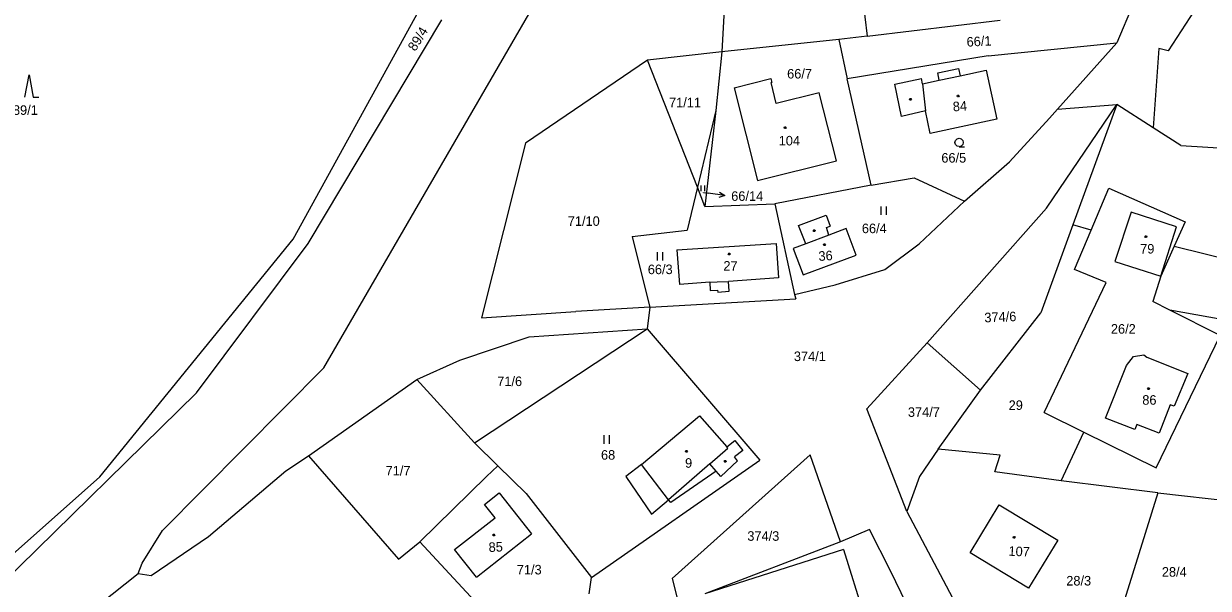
# Model space of a CAD drawing. Extents: x -811039 to -805820, y -1161436 to -1155864.
# Drawn here: x -806771.7 to -806560.9, y -1158236.2 to -1158135.7 of the extents above; entities that cross this region are included whole.
import ezdxf

# ---------------------------------------------------------------- set-up
doc = ezdxf.new("R2010")
doc.units = 0
for name, color, linetype in [('Default', 7, 'Continuous'), ('KN_HRANICE', 7, 'Continuous'), ('KN_KULTURY', 7, 'Continuous'), ('KN_PARCELY', 7, 'Continuous'), ('KN_SLUCKY', 7, 'Continuous')]:
    doc.layers.add(name, color=color, linetype=linetype)

# ---------------------------------------------------------------- blocks, each defined once
blk = doc.blocks.new('304')
at = {"layer": 'Default'}
blk.add_lwpolyline([(0, 0), (-0.38, 0.1), (-0.65, 0.37), (-0.75, 0.74), (-0.65, 1.11), (-0.38, 1.38), (-0.01, 1.48), (0.36, 1.38), (0.63, 1.11), (0.73, 0.73), (0.63, 0.35), (0.36, 0.08), (-0.02, -0.02), (0.98, -0.02)], dxfattribs=at)
blk = doc.blocks.new('306')
at = {"layer": 'Default'}
for p, q in [((-0.5, 1.5), (-0.5, 0)), ((0.5, 0), (0.5, 1.5))]:
    blk.add_line(p, q, dxfattribs=at)
blk = doc.blocks.new('308')
at = {"layer": 'Default'}
blk.add_lwpolyline([(-0.75, 0), (0, 4), (0.75, 0), (1.75, 0)], dxfattribs=at)
blk = doc.blocks.new('10292')
at = {"layer": 'Default'}
blk.add_line((0, 3), (0, 0), dxfattribs=at)
blk.add_lwpolyline([(-0.5, 2), (0, 3), (0.5, 2)], dxfattribs=at)
blk = doc.blocks.new('402')
at = {"layer": 'Default'}
blk.add_lwpolyline([(0.09, 0.15), (0.18, 0), (0.09, -0.15), (-0.09, -0.15), (-0.18, 0), (-0.09, 0.15), (0.09, 0.15)], dxfattribs=at)

msp = doc.modelspace()

# ---------------------------------------------------------------- linework, layer by layer
at = {"layer": 'KN_HRANICE'}
for p, q in [((-806625.5, -1158104.42), (-806621.6, -1158137.92)), ((-806723.74, -1158174.06), (-806693.13, -1158118.44)), ((-806646.33, -1158121.28), (-806647.48, -1158140.75)), ((-806558.78, -1158126.18), (-806568.02, -1158140.53)), ((-806718.26, -1158196.99), (-806677.82, -1158127.15)), ((-806574.25, -1158132.24), (-806577.2, -1158139.11)), ((-806721.04, -1158174.85), (-806697.27, -1158135.03)), ((-806621.6, -1158137.92), (-806597.92, -1158135.1)), ((-806626.66, -1158138.55), (-806647.48, -1158140.75)), ((-806621.6, -1158137.92), (-806626.66, -1158138.55)), ((-806626.66, -1158138.55), (-806625.14, -1158145.51)), ((-806600.08, -1158141.46), (-806577.2, -1158139.11)), ((-806587.74, -1158150.92), (-806577.2, -1158139.11)), ((-806647.48, -1158140.75), (-806660.66, -1158142.19)), ((-806647.48, -1158140.75), (-806648.51, -1158151.16)), ((-806569.67, -1158140.13), (-806570.68, -1158154.28)), ((-806568.02, -1158140.53), (-806569.67, -1158140.13)), ((-806660.66, -1158142.19), (-806682.39, -1158156.98)), ((-806651.8, -1158164.84), (-806660.66, -1158142.19)), ((-806600.08, -1158141.46), (-806625.14, -1158145.51)), ((-806645.27, -1158147.12), (-806638.76, -1158145.49)), ((-806638.76, -1158145.49), (-806638.59, -1158146.19)), ((-806620.86, -1158164.46), (-806625.14, -1158145.51)), ((-806616.67, -1158146.5), (-806611.94, -1158145.48)), ((-806611.75, -1158146.41), (-806611.94, -1158145.48)), ((-806609.04, -1158144.44), (-806605.35, -1158143.69)), ((-806608.8, -1158145.74), (-806609.04, -1158144.44)), ((-806605.35, -1158143.69), (-806605.07, -1158144.98)), ((-806605.07, -1158144.98), (-806600.43, -1158143.97)), ((-806600.43, -1158143.97), (-806598.53, -1158152.7)), ((-806645.27, -1158147.12), (-806641.11, -1158163.62)), ((-806638.59, -1158146.19), (-806638.69, -1158146.21)), ((-806637.77, -1158149.94), (-806638.69, -1158146.21)), ((-806615.49, -1158152.21), (-806616.67, -1158146.5)), ((-806611.75, -1158146.41), (-806608.8, -1158145.74)), ((-806630.11, -1158148.03), (-806637.77, -1158149.94)), ((-806627.08, -1158160.11), (-806630.11, -1158148.03)), ((-806648.51, -1158151.16), (-806651.8, -1158164.84)), ((-806648.51, -1158151.16), (-806650.46, -1158168.28)), ((-806611.24, -1158151.25), (-806615.49, -1158152.21)), ((-806610.39, -1158155.24), (-806611.24, -1158151.25)), ((-806589.71, -1158168.58), (-806577.19, -1158150.1)), ((-806589.16, -1158152.51), (-806587.74, -1158150.92)), ((-806587.74, -1158150.92), (-806577.19, -1158150.1)), ((-806577.19, -1158150.1), (-806584.99, -1158171.53)), ((-806570.68, -1158154.28), (-806577.19, -1158150.1)), ((-806598.53, -1158152.7), (-806610.39, -1158155.24)), ((-806596.26, -1158160.32), (-806589.16, -1158152.51)), ((-806565.79, -1158157.41), (-806570.68, -1158154.28)), ((-806682.39, -1158156.98), (-806690.22, -1158188.05)), ((-806565.79, -1158157.41), (-806554.8, -1158158.09)), ((-806641.11, -1158163.62), (-806627.08, -1158160.11)), ((-806604.3, -1158167.3), (-806596.26, -1158160.32)), ((-806620.86, -1158164.46), (-806638, -1158167.77)), ((-806620.86, -1158164.46), (-806613.26, -1158163.16)), ((-806613.26, -1158163.16), (-806604.3, -1158167.3)), ((-806651.8, -1158164.84), (-806653.63, -1158172.45)), ((-806650.46, -1158168.28), (-806651.8, -1158164.84)), ((-806581.74, -1158172.46), (-806578.57, -1158164.97)), ((-806578.57, -1158164.97), (-806565.02, -1158170.97)), ((-806650.46, -1158168.28), (-806638, -1158167.77)), ((-806638, -1158167.77), (-806634.51, -1158183.94)), ((-806604.3, -1158167.3), (-806612.34, -1158174.92)), ((-806610.94, -1158192.5), (-806589.71, -1158168.58)), ((-806633.81, -1158171.63), (-806628.89, -1158169.81)), ((-806628.89, -1158169.81), (-806628.2, -1158171.77)), ((-806574.65, -1158169.26), (-806577.5, -1158178.04)), ((-806566.53, -1158171.88), (-806574.65, -1158169.26)), ((-806663.42, -1158173.62), (-806653.63, -1158172.45)), ((-806632.51, -1158174.87), (-806633.81, -1158171.63)), ((-806628.81, -1158171.99), (-806628.2, -1158171.77)), ((-806628.42, -1158173.33), (-806628.81, -1158171.99)), ((-806625.31, -1158172.15), (-806628.42, -1158173.33)), ((-806623.58, -1158176.91), (-806625.31, -1158172.15)), ((-806584.99, -1158171.53), (-806590.67, -1158187.16)), ((-806581.74, -1158172.46), (-806584.99, -1158171.53)), ((-806584.71, -1158179.46), (-806581.74, -1158172.46)), ((-806569.37, -1158180.66), (-806566.53, -1158171.88)), ((-806565.02, -1158170.97), (-806566.96, -1158175.3)), ((-806758.12, -1158216.37), (-806723.74, -1158174.06)), ((-806740.96, -1158201.43), (-806721.04, -1158174.85)), ((-806663.42, -1158173.62), (-806661.2, -1158182.44)), ((-806655.48, -1158175.94), (-806637.79, -1158174.85)), ((-806637.79, -1158174.85), (-806637.37, -1158180.94)), ((-806632.51, -1158174.87), (-806634.77, -1158175.72)), ((-806618.45, -1158179.46), (-806612.34, -1158174.92)), ((-806655.48, -1158175.94), (-806654.99, -1158182.11)), ((-806634.77, -1158175.72), (-806633.01, -1158180.44)), ((-806633.01, -1158180.44), (-806623.58, -1158176.91)), ((-806566.96, -1158175.3), (-806569.37, -1158180.66)), ((-806566.96, -1158175.3), (-806533.49, -1158183.62)), ((-806577.5, -1158178.04), (-806569.37, -1158180.66)), ((-806637.37, -1158180.94), (-806646.27, -1158181.59)), ((-806627.29, -1158182.21), (-806618.45, -1158179.46)), ((-806579.07, -1158181.81), (-806584.71, -1158179.46)), ((-806569.37, -1158180.66), (-806570.79, -1158185.17)), ((-806661.2, -1158182.44), (-806660.25, -1158186.2)), ((-806649.57, -1158181.75), (-806654.99, -1158182.11)), ((-806649.57, -1158181.75), (-806649.53, -1158183.19)), ((-806649.53, -1158183.19), (-806648.24, -1158183.14)), ((-806648.24, -1158183.14), (-806648.19, -1158183.48)), ((-806648.19, -1158183.48), (-806646.13, -1158183.34)), ((-806646.13, -1158183.34), (-806646.27, -1158181.59)), ((-806634.51, -1158183.94), (-806627.29, -1158182.21)), ((-806590.13, -1158204.94), (-806579.07, -1158181.81)), ((-806660.25, -1158186.2), (-806634.28, -1158184.71)), ((-806634.51, -1158183.94), (-806634.28, -1158184.71)), ((-806567.76, -1158186.7), (-806570.79, -1158185.17)), ((-806690.22, -1158188.05), (-806673.44, -1158186.95)), ((-806660.25, -1158186.2), (-806673.44, -1158186.95)), ((-806660.25, -1158186.2), (-806660.73, -1158190.04)), ((-806601.46, -1158200.93), (-806590.67, -1158187.16)), ((-806535.97, -1158192.47), (-806567.76, -1158186.7)), ((-806558.81, -1158191.24), (-806567.76, -1158186.7)), ((-806694.06, -1158195.61), (-806681.77, -1158191.44)), ((-806691.48, -1158210.33), (-806660.73, -1158190.04)), ((-806681.77, -1158191.44), (-806660.73, -1158190.04)), ((-806660.73, -1158190.04), (-806640.69, -1158213.39)), ((-806570.15, -1158214.79), (-806558.81, -1158191.24)), ((-806621.66, -1158204.29), (-806610.94, -1158192.5)), ((-806610.94, -1158192.5), (-806601.46, -1158200.93)), ((-806701.73, -1158199.05), (-806694.06, -1158195.61)), ((-806575.43, -1158196.54), (-806574.21, -1158194.95)), ((-806574.21, -1158194.95), (-806572.39, -1158194.67)), ((-806572.39, -1158194.67), (-806571.82, -1158195.06)), ((-806571.82, -1158195.06), (-806564.52, -1158198.01)), ((-806746.97, -1158225.93), (-806718.26, -1158196.99)), ((-806579.19, -1158205.91), (-806575.43, -1158196.54)), ((-806564.52, -1158198.01), (-806566.95, -1158203.82)), ((-806720.99, -1158212.66), (-806701.73, -1158199.05)), ((-806701.73, -1158199.05), (-806691.48, -1158210.33)), ((-806775.62, -1158235.5), (-806740.96, -1158201.43)), ((-806608.94, -1158211.47), (-806601.46, -1158200.93)), ((-806614.52, -1158222.57), (-806621.66, -1158204.29)), ((-806567.68, -1158203.57), (-806569.64, -1158208.59)), ((-806566.95, -1158203.82), (-806567.68, -1158203.57)), ((-806661.77, -1158214.18), (-806651.42, -1158205.5)), ((-806651.42, -1158205.5), (-806646.58, -1158211.03)), ((-806590.13, -1158204.94), (-806583.06, -1158208.43)), ((-806573.94, -1158207.94), (-806579.19, -1158205.91)), ((-806587.07, -1158217.11), (-806583.06, -1158208.43)), ((-806583.06, -1158208.43), (-806570.15, -1158214.79)), ((-806573.6, -1158207.07), (-806573.94, -1158207.94)), ((-806569.64, -1158208.59), (-806573.6, -1158207.07)), ((-806691.48, -1158210.33), (-806687.32, -1158214.39)), ((-806646.58, -1158211.03), (-806645.13, -1158209.88)), ((-806645.13, -1158209.88), (-806643.73, -1158211.67)), ((-806725.06, -1158215.32), (-806720.99, -1158212.66)), ((-806720.99, -1158212.66), (-806704.99, -1158231.03)), ((-806631.74, -1158212.47), (-806656.32, -1158234.5)), ((-806643.73, -1158211.67), (-806645.19, -1158212.83)), ((-806644.67, -1158213.5), (-806645.19, -1158212.83)), ((-806626.33, -1158227.96), (-806631.74, -1158212.47)), ((-806608.94, -1158211.47), (-806612.29, -1158216.31)), ((-806597.93, -1158212.53), (-806608.94, -1158211.47)), ((-806598.86, -1158215.46), (-806597.93, -1158212.53)), ((-806689.31, -1158216.34), (-806687.32, -1158214.39)), ((-806687.32, -1158214.39), (-806682.28, -1158219.32)), ((-806670.66, -1158234.29), (-806640.69, -1158213.39)), ((-806661.77, -1158214.18), (-806664.55, -1158216.31)), ((-806644.67, -1158213.5), (-806647.64, -1158216.31)), ((-806777.52, -1158233.56), (-806758.12, -1158216.37)), ((-806738.78, -1158227.02), (-806725.06, -1158215.32)), ((-806701.18, -1158227.97), (-806689.31, -1158216.34)), ((-806664.55, -1158216.31), (-806659.95, -1158223)), ((-806648.46, -1158215.37), (-806656.52, -1158220.93)), ((-806647.64, -1158216.31), (-806648.46, -1158215.37)), ((-806612.29, -1158216.31), (-806614.52, -1158222.57)), ((-806587.07, -1158217.11), (-806598.86, -1158215.46)), ((-806569.88, -1158219.21), (-806587.07, -1158217.11)), ((-806689.66, -1158221.29), (-806687.05, -1158219.25)), ((-806687.05, -1158219.25), (-806681.35, -1158226.55)), ((-806682.28, -1158219.32), (-806670.66, -1158234.29)), ((-806569.88, -1158219.21), (-806579.62, -1158250.35)), ((-806569.88, -1158219.21), (-806553.85, -1158221)), ((-806687.79, -1158223.66), (-806689.66, -1158221.29)), ((-806659.95, -1158223), (-806656.92, -1158220.46)), ((-806656.52, -1158220.93), (-806656.92, -1158220.46)), ((-806603.29, -1158229.88), (-806598.12, -1158221.34)), ((-806598.12, -1158221.34), (-806587.68, -1158227.66)), ((-806614.52, -1158222.57), (-806600.61, -1158248.81)), ((-806695.01, -1158229.34), (-806687.79, -1158223.66)), ((-806750.61, -1158231.75), (-806746.97, -1158225.93)), ((-806749, -1158233.96), (-806738.78, -1158227.02)), ((-806691.11, -1158234.24), (-806681.35, -1158226.55)), ((-806621.17, -1158225.74), (-806626.33, -1158227.96)), ((-806617.42, -1158233.13), (-806621.17, -1158225.74)), ((-806587.68, -1158227.66), (-806592.88, -1158236.19)), ((-806704.99, -1158231.03), (-806701.18, -1158227.97)), ((-806701.18, -1158227.97), (-806684.08, -1158246.35)), ((-806691.11, -1158234.24), (-806695.01, -1158229.34)), ((-806626.33, -1158227.96), (-806650.49, -1158237.2)), ((-806625.78, -1158229.31), (-806650.49, -1158237.2)), ((-806625.78, -1158229.31), (-806618.07, -1158254.33)), ((-806592.88, -1158236.19), (-806603.29, -1158229.88)), ((-806751.34, -1158233.56), (-806750.61, -1158231.75)), ((-806766.34, -1158245.5), (-806751.34, -1158233.56)), ((-806751.34, -1158233.56), (-806749, -1158233.96)), ((-806611.64, -1158244.97), (-806617.42, -1158233.13)), ((-806671.05, -1158237.22), (-806670.66, -1158234.29)), ((-806656.32, -1158234.5), (-806655.17, -1158238.94))]:
    msp.add_line(p, q, dxfattribs=at)
at = {"layer": 'KN_PARCELY'}
msp.add_line((-806650.72, -1158165.79), (-806649.91, -1158165.9), dxfattribs=at)
at = {"layer": 'KN_SLUCKY'}
for p, q in [((-806608.8, -1158145.74), (-806605.07, -1158144.98)), ((-806611.75, -1158146.41), (-806611.24, -1158151.25)), ((-806628.42, -1158173.33), (-806632.51, -1158174.87)), ((-806649.57, -1158181.75), (-806648.29, -1158181.69)), ((-806648.29, -1158181.69), (-806646.27, -1158181.59)), ((-806649.62, -1158214.09), (-806646.38, -1158211.26)), ((-806646.38, -1158211.26), (-806646.58, -1158211.03)), ((-806656.92, -1158220.46), (-806661.77, -1158214.18)), ((-806649.62, -1158214.09), (-806656.92, -1158220.46)), ((-806648.46, -1158215.37), (-806649.62, -1158214.09))]:
    msp.add_line(p, q, dxfattribs=at)

# ---------------------------------------------------------------- block references
at = {"layer": 'KN_KULTURY'}
for name, p in [('308', (-806770.74, -1158148.79)), ('402', (-806613.91, -1158149.19)), ('402', (-806605.42, -1158148.58)), ('402', (-806636.2, -1158154.2)), ('304', (-806605.23, -1158157.59)), ('306', (-806618.66, -1158169.75)), ('402', (-806631.02, -1158172.53)), ('402', (-806629.2, -1158175.03)), ('402', (-806571.99, -1158173.61)), ('306', (-806658.48, -1158177.87)), ('402', (-806646.14, -1158176.69)), ('402', (-806571.53, -1158200.7)), ('306', (-806667.94, -1158210.48)), ('402', (-806653.75, -1158211.83)), ('402', (-806646.86, -1158213.62)), ('402', (-806688.03, -1158226.72)), ('402', (-806595.45, -1158227.17))]:
    msp.add_blockref(name, p, dxfattribs=at)
at = {"layer": 'KN_KULTURY', "xscale": 0.67, "yscale": 0.67}
msp.add_blockref('306', (-806650.84, -1158165.53), dxfattribs=at)
at = {"layer": 'KN_PARCELY', "rotation": -97.98640000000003}
msp.add_blockref('10292', (-806649.91, -1158165.9), dxfattribs=at)

# ---------------------------------------------------------------- texts
at = {"layer": 'KN_PARCELY'}
for s, rotation, p in [('89/4', 58.213, (-806702, -1158140.74)), ('66/1', 2.865, (-806603.86, -1158139.81)), ('84', 3.896, (-806606.3, -1158151.33)), ('36', 3.667, (-806630.21, -1158177.95)), ('66/3', 0.172, (-806660.63, -1158180.3)), ('27', 359.073, (-806647.2, -1158179.66)), ('374/6', 2.292, (-806600.71, -1158188.88)), ('85', 2.578, (-806688.92, -1158229.76)), ('107', 357.354, (-806596.48, -1158230.41))]:
    msp.add_text(s, height=1.7, rotation=rotation, dxfattribs=at).set_placement(p)
for s, height, p in [('66/7', 1.7, (-806635.84, -1158145.47)), ('71/11', 1.7, (-806656.85, -1158150.58)), ('89/1', 1.7, (-806773.6, -1158151.94)), ('104', 1.7, (-806637.34, -1158157.39)), ('66/5', 1.7, (-806608.4, -1158160.44)), ('66/14', 0.1, (-806650.97, -1158165.79)), ('66/14', 1.7, (-806645.79, -1158167.25)), ('71/10', 1.7, (-806674.87, -1158171.7)), ('66/4', 1.7, (-806622.54, -1158173)), ('79', 1.7, (-806573.02, -1158176.63)), ('26/2', 1.7, (-806578.23, -1158190.89)), ('374/1', 1.7, (-806634.64, -1158195.77)), ('71/6', 1.7, (-806687.42, -1158200.22)), ('86', 1.7, (-806572.64, -1158203.54)), ('374/7', 1.7, (-806614.35, -1158205.7)), ('29', 1.7, (-806596.42, -1158204.47)), ('68', 1.7, (-806668.96, -1158213.32)), ('9', 1.7, (-806654, -1158214.76)), ('71/7', 1.7, (-806707.28, -1158216.13)), ('374/3', 1.7, (-806642.92, -1158227.76)), ('71/3', 1.7, (-806683.94, -1158233.75)), ('28/3', 1.7, (-806586.17, -1158235.72)), ('28/4', 1.7, (-806569.16, -1158234.15))]:
    msp.add_text(s, height=height, dxfattribs=at).set_placement(p)

doc.saveas('drawing.dxf')
